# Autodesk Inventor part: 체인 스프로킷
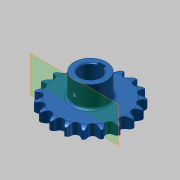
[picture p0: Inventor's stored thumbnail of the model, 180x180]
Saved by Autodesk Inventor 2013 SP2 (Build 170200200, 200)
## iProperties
Created: 2014-11
Part Number: 체인 스프로킷
Material: 강
Document SubType Name: Modeling
Designer: KYOUNG IL JANG
Density: 7.85 g/cm^3
Mass: 738.264 g
Surface Area: 236.923 cm^2
Volume: 94.0463 cm^3
CustomPartVersion: 1
Company: 한국ATC센터
Author: KYOUNG IL JANG
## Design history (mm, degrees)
sketch "이론적 톱니 프로파일"
  geometry: L1 (0, 0)-(0, 45.567); L2 (0, 0)-(14.795, 43.098); L3 (0, 45.567)-(14.795, 43.098); L4 (0, 45.567)-(5.661, 50.015); L5 (5.661, 50.015)-(-5.141, 45.406); L6 (-12.428, 43.493)-(-5.573, 46.417); L7 (-5.141, 45.406)-(-5.573, 46.417); L8 (5.573, 46.417)-(5.141, 45.406); L9 (0, 0)-(8.138, 48.771); A1 r 45.567 centre (0, 0) between (0, 45.567) and (14.795, 43.098); A2 r 49.445 centre (0, 0) between (7.302, 48.903) and (-7.302, 48.903); A3 r 4.545 centre (0, 45.567) between (-3.574, 42.758) and (3.574, 42.758); A4 r 7.453 centre (12.428, 43.493) between (7.302, 48.903) and (5.573, 46.417); A5 r 7.453 centre (-12.428, 43.493) between (-5.573, 46.417) and (-7.302, 48.903); A6 r 11.745 centre (5.661, 50.015) between (-5.141, 45.406) and (-3.574, 42.758); A7 r 11.745 centre (-5.661, 50.015) between (3.574, 42.758) and (5.141, 45.406); 2 further points
  constraints: 18 end point, 15 point on circle, 7 centre point, 3 coincident, 3 point on line, 3 symmetric about line, 3 tangent, 1 equal radius, 1 midpoint, 1 parallel, 1 vertical, 1 other
  dimensions: "d0" = 91.13301 diameter of A1 (computed from da_p, da_z); "d2" = 18.9474 deg angle of L2 L1 (computed from da_z); "d3" = 4.545 radius of A3 (= 0.5 x da_Dr + da_SC); "d10" = 128.158 deg angle of L4 L1 (computed from da_z); "d11" = 15.0526 deg angle of L5 L4 (computed from da_z); "d12" = 7.2 distance of L3.start L4.end (= 0.8 x da_Dr); "d13" = 11.745 distance of L4.end L5.end (= 1.3 x da_Dr + da_SC); "d14" = 12.6 distance of A4.centre L1.end (= 1.4 x da_Dr); "d23" = 4.5 distance from line of L9.end L3 (= da_Ha)
sketch "톱니 프로파일"
  geometry: L1 (0, 0)-(0, 45.567); L2 (0, 45.567)-(4.203, 43.837); L3 (0, 45.567)-(-4.203, 43.837); A1 r 4.545 centre (0, 45.567) between (-4.203, 43.837) and (4.203, 43.837); A2 r 22.68 centre (25.176, 35.206) between (7.12, 48.93) and (4.203, 43.837); A3 r 22.68 centre (-25.176, 35.206) between (-4.203, 43.837) and (-7.12, 48.93); A4 r 49.445 centre (0, 0) between (-7.12, 48.93) and (7.12, 48.93) reference; 1 further point
  constraints: 9 point on circle, 6 end point, 3 centre point, 2 tangent, 1 coincident, 1 equal radius, 1 vertical, 1 other
  dimensions: "d44" = 135.263 deg angle of L3 L2 (= da_Alfa); "d45" = 22.68 radius of A2 (= da_Re); "d46" = 4.545 radius of A1 (= da_Ri)
sketch "단면 프로파일"
  geometry: L1 (49.445, 0)-(-49.445, 0) reference; L2 (33.265, 6.65)-(-33.265, 6.65); L3 (-33.265, 6.65)-(-33.265, -6.65); L4 (-33.265, -6.65)-(33.265, -6.65); L5 (33.265, -6.65)-(33.265, 6.65); L6 (33.265, 6.65)-(49.445, 6.65); L7 (49.445, 6.65)-(49.445, -6.65); L8 (49.445, -6.65)-(33.265, -6.65); L9 (33.265, -6.65)-(33.265, 6.65); L10 (42.183, 6.65)-(0, 6.65); L11 (0, 6.65)-(0, -6.65); L12 (0, -6.65)-(42.183, -6.65); L13 (0, 6.65)-(0, -6.65); L14 (49.445, 4.775)-(49.445, -4.775); A1 r 15 centre (42.183, -8.35) between (49.445, 4.775) and (42.183, 6.65); A2 r 15 centre (42.183, 8.35) between (42.183, -6.65) and (49.445, -4.775); 2 further points
  constraints: 26 end point, 7 midpoint, 5 perpendicular, 4 parallel, 4 point on circle, 3 point on line, 3 symmetric about line, 2 centre point, 2 horizontal, 2 tangent, 1 collinear, 1 other
  dimensions: "d30" = 13.3 distance between parallel lines of L8 L6 (= da_Bf); "d31" = 66.53007 distance between parallel lines of L3 L5 (= da_Ds); "d32" = 13.3 distance between parallel lines of L4 L2 (= da_Bs); "d33" = 1.875 distance from line of L14.start L6 (= da_Ba); "d34" = 15 radius of A1 (= da_Rx); "d43" = 6.65 distance between parallel lines of L4 L1 (computed from da_k, da_pt, da_Bs)
revolve "슈라우드" stored, may be unused: angle "d36" = 90 deg
revolve "스트랜드" stored, may be unused: angle "d37" = 90 deg
extrude "이론적 톱니" cut sketch "이론적 톱니 프로파일" stored distance "d18" = 10; taper "d19" = 0 deg; dims "d49" = 0, "form_type" = 0 [user parameter]
extrude "톱니" cut sketch "톱니 프로파일" stored distance "d47" = 10; taper "d48" = 0 deg; dims "d50" = 10, "form_type" = 0 [user parameter]
node "타이밍 평면"
node "작업 평면3"
sketch "스케치5"
  geometry: C1 r 20 at (0, -45.567); 1 further point
  constraints: 1 centre point, 1 coincident
  dimensions: "d52" = 40 diameter of C1
extrude "돌출4" join sketch "스케치5" stored distance "d53" = 10; taper "d54" = 0 deg
sketch "스케치6"
  geometry: L1 (4, 11.843)-(4, 16.5); L2 (4, 16.5)-(-4, 16.5); L3 (-4, 16.5)-(-4, 11.843); A1 r 12.5 centre (0, 0) between (4, 11.843) and (-4, 11.843); 1 further point
  constraints: 6 end point, 2 parallel, 2 point on circle, 1 centre point, 1 coincident, 1 perpendicular, 1 vertical
  dimensions: "d55" = 25 diameter of A1; "d56" = 29 dimension on A1 L2 (computed from d55); "d57" = 8 distance of L1.end L2.end
extrude "돌출5" cut sketch "스케치6" stored distance "d58" = 10; taper "d59" = 0 deg
fillet "모깎기2" dims "d60" = 3
chamfer "모따기1" distance "d61" = 1; stored, may be unused: second distance "d62" = 2, angle "d63" = 45 deg
node "작업 평면4"
sketch "스케치7"
  geometry: L1 (-13.5, -13.3)-(13.5, -13.3) reference; 4 further points
  constraints: 1 vertical alignment
  dimensions: "d65" = 25 distance from line of point (0, 11.7) L1
hole "구멍1" sketch "스케치7" at (0, 11.7) diameter "d66" = 5; stored, may be unused: countersink angle "d70" = 90 deg, drill point angle "d72" = 118 deg; dims "d67" = 6, "d68" = 4, "d69" = 2, "d71" = 8
feature "스레드1" dims "d73" = 10, "d74" = 0
body "Solid1"
pattern_linear "스트랜드 패턴" dims "d40" = 24 (= da_pt)
pattern_circular "톱니 패턴" dims angle "d21" = 360 deg
other parameters: "da_p" = 15 [user parameter; used in 1 equation term], "da_Dr" = 9 [user parameter; used in 4 equation terms], "da_SC" = 0.045 [user parameter; used in 2 equation terms], "da_Ha" = 4.5 [user parameter; used in 1 equation term], "da_pt" = 24 [user parameter; used in 2 equation terms], "da_Bf" = 13.3 [user parameter; used in 1 equation term], "d28" = 0, "d29" = 0, "da_Ba" = 1.875 [user parameter; used in 1 equation term], "da_Rx" = 15 [user parameter; used in 1 equation term], "da_Ra" = 0.6 [user parameter], "da_Bs" = 13.3 [user parameter; used in 2 equation terms], "da_Ds" = 66.53007 [user parameter; used in 1 equation term], "d42" = 0, "da_Re" = 22.68 [user parameter; used in 1 equation term], "da_Ri" = 4.545 [user parameter; used in 1 equation term], "da_Alfa" = 135.263 deg [user parameter; used in 1 equation term]
